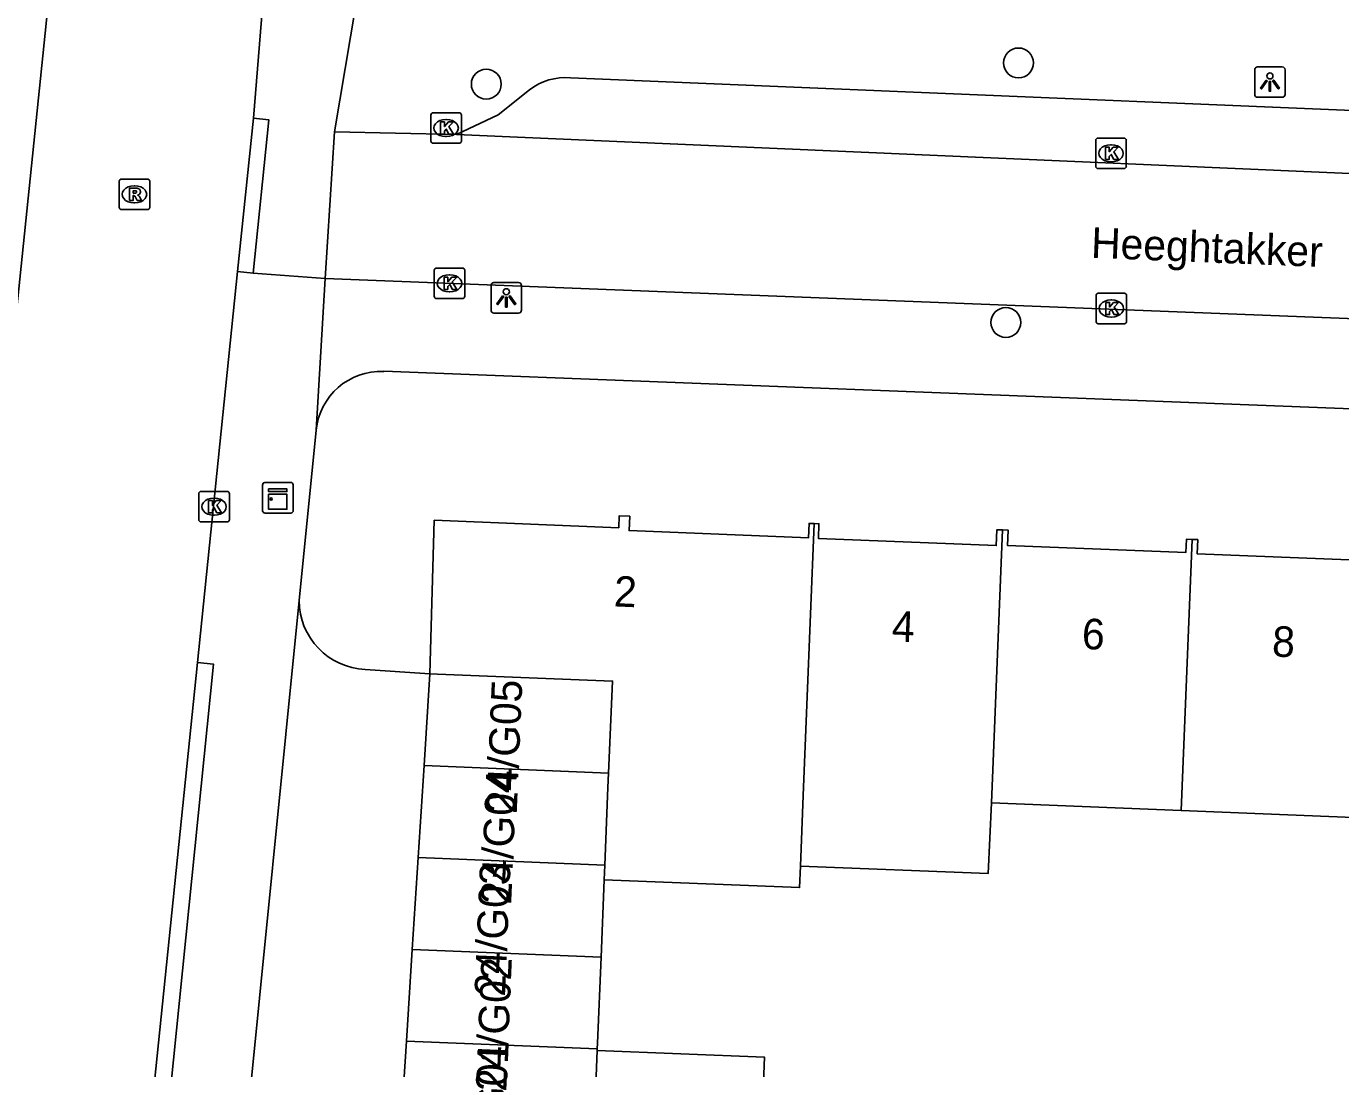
# Model space of a CAD drawing. Extents: x 161355 to 162026, y 386504 to 387459.
# Drawn here: x 161823.29 to 161866.31, y 387026.14 to 387060.25 of the extents above; entities that cross this region are included whole.
import ezdxf

# ---------------------------------------------------------------- set-up
doc = ezdxf.new("R2010")
doc.units = 0
for name, color, linetype in [('IMGEO_Boom', 7, 'Continuous'), ('IMGEO_Kast', 7, 'Continuous'), ('IMGEO_Kolk', 7, 'Continuous'), ('IMGEO_Lichtpunt', 7, 'Continuous'), ('IMGEO_Openbare_ruimte_label', 7, 'Continuous'), ('IMGEO_Pand', 7, 'Continuous'), ('IMGEO_Pand_nummerreeks', 7, 'Continuous'), ('IMGEO_Rijbaan_lokaal_open', 7, 'Continuous'), ('IMGEO_Rioolput', 7, 'Continuous'), ('IMGEO_Voetpad_open', 7, 'Continuous')]:
    doc.layers.add(name, color=color, linetype=linetype)

msp = doc.modelspace()

# ---------------------------------------------------------------- linework, layer by layer
at = {"layer": 'IMGEO_Boom'}
for centre in [(161855.765, 387059.053), (161838.346, 387058.361), (161855.351, 387050.56)]:
    msp.add_circle(centre, 0.489, dxfattribs=at)
at = {"layer": 'IMGEO_Kast'}
for p, q in [((161831.026, 387044.398), (161831.026, 387045.239)), ((161831.026, 387045.239), (161831.026, 387044.398)), ((161831.101, 387045.323), (161831.942, 387045.323)), ((161831.942, 387045.323), (161831.101, 387045.323)), ((161832.026, 387045.248), (161832.026, 387044.407)), ((161832.026, 387044.407), (161832.026, 387045.248)), ((161831.951, 387044.323), (161831.11, 387044.323)), ((161831.11, 387044.323), (161831.951, 387044.323))]:
    msp.add_line(p, q, dxfattribs=at)
for points in [[(161831.221, 387045.113), (161831.821, 387045.113), (161831.821, 387045.028), (161831.221, 387045.028), (161831.221, 387045.113)], [(161831.221, 387044.938), (161831.821, 387044.938), (161831.821, 387044.449), (161831.221, 387044.449), (161831.221, 387044.938)]]:
    msp.add_lwpolyline(points, dxfattribs=at)
msp.add_circle((161831.305, 387044.787), 0.0377, dxfattribs=at)
for centre, start, end in [((161831.104, 387045.245), 92.4484, 184.2845), ((161831.104, 387045.245), 92.4484, 184.2845), ((161831.948, 387045.245), 2.4484, 94.2845), ((161831.948, 387045.245), 2.4484, 94.2845), ((161831.104, 387044.401), 182.4484, 274.2845), ((161831.104, 387044.401), 182.4484, 274.2845), ((161831.948, 387044.401), 272.4484, 4.2845), ((161831.948, 387044.401), 272.4484, 4.2845)]:
    msp.add_arc(centre, 0.0779, start, end, dxfattribs=at)
at = {"layer": 'IMGEO_Kolk'}
for p, q in [((161836.605, 387057.424), (161837.457, 387057.424)), ((161836.53, 387056.498), (161836.53, 387057.35)), ((161837.018, 387057.204), (161837.043, 387057.204)), ((161837.531, 387057.35), (161837.531, 387056.498)), ((161837.041, 387056.644), (161837.016, 387056.644)), ((161858.293, 387055.67), (161858.293, 387056.522)), ((161858.368, 387056.596), (161859.22, 387056.596)), ((161859.294, 387056.522), (161859.294, 387055.67)), ((161837.457, 387056.424), (161836.605, 387056.424)), ((161858.781, 387056.376), (161858.806, 387056.376)), ((161858.804, 387055.816), (161858.779, 387055.816)), ((161859.22, 387055.596), (161858.368, 387055.596)), ((161836.642, 387051.416), (161836.642, 387052.268)), ((161836.717, 387052.342), (161837.569, 387052.342)), ((161837.643, 387052.268), (161837.643, 387051.416)), ((161837.13, 387052.122), (161837.155, 387052.122)), ((161837.153, 387051.562), (161837.128, 387051.562)), ((161858.302, 387050.591), (161858.302, 387051.443)), ((161858.377, 387051.517), (161859.229, 387051.517)), ((161859.303, 387051.443), (161859.303, 387050.591)), ((161837.569, 387051.342), (161836.717, 387051.342)), ((161858.79, 387051.297), (161858.815, 387051.297)), ((161859.229, 387050.517), (161858.377, 387050.517)), ((161858.813, 387050.737), (161858.788, 387050.737)), ((161828.936, 387044.105), (161828.936, 387044.957)), ((161829.011, 387045.031), (161829.863, 387045.031)), ((161829.937, 387044.957), (161829.937, 387044.105)), ((161829.424, 387044.811), (161829.449, 387044.811)), ((161829.447, 387044.251), (161829.422, 387044.251)), ((161829.863, 387044.031), (161829.011, 387044.031))]:
    msp.add_line(p, q, dxfattribs=at)
for points in [[(161836.605, 387057.424), (161837.457, 387057.424)], [(161836.53, 387056.498), (161836.53, 387057.35)], [(161836.851, 387057.124), (161836.974, 387057.124), (161836.974, 387056.973), (161837.104, 387057.124), (161837.268, 387057.124), (161837.122, 387056.973), (161837.275, 387056.724), (161837.123, 387056.724), (161837.038, 387056.888), (161836.974, 387056.821), (161836.974, 387056.724), (161836.851, 387056.724), (161836.851, 387057.124)], [(161837.531, 387057.35), (161837.531, 387056.498)], [(161858.293, 387055.67), (161858.293, 387056.522)], [(161858.368, 387056.596), (161859.22, 387056.596)], [(161859.294, 387056.522), (161859.294, 387055.67)], [(161837.457, 387056.424), (161836.605, 387056.424)], [(161858.614, 387056.296), (161858.737, 387056.296), (161858.737, 387056.145), (161858.867, 387056.296), (161859.031, 387056.296), (161858.885, 387056.145), (161859.038, 387055.896), (161858.886, 387055.896), (161858.801, 387056.06), (161858.737, 387055.993), (161858.737, 387055.896), (161858.614, 387055.896), (161858.614, 387056.296)], [(161859.22, 387055.596), (161858.368, 387055.596)], [(161836.642, 387051.416), (161836.642, 387052.268)], [(161836.717, 387052.342), (161837.569, 387052.342)], [(161837.643, 387052.268), (161837.643, 387051.416)], [(161836.963, 387052.042), (161837.086, 387052.042), (161837.086, 387051.891), (161837.216, 387052.042), (161837.38, 387052.042), (161837.234, 387051.891), (161837.387, 387051.642), (161837.235, 387051.642), (161837.15, 387051.806), (161837.086, 387051.739), (161837.086, 387051.642), (161836.963, 387051.642), (161836.963, 387052.042)], [(161858.302, 387050.591), (161858.302, 387051.443)], [(161858.377, 387051.517), (161859.229, 387051.517)], [(161859.303, 387051.443), (161859.303, 387050.591)], [(161837.569, 387051.342), (161836.717, 387051.342)], [(161858.623, 387051.217), (161858.746, 387051.217), (161858.746, 387051.066), (161858.876, 387051.217), (161859.04, 387051.217), (161858.894, 387051.066), (161859.047, 387050.817), (161858.895, 387050.817), (161858.81, 387050.981), (161858.746, 387050.914), (161858.746, 387050.817), (161858.623, 387050.817), (161858.623, 387051.217)], [(161859.229, 387050.517), (161858.377, 387050.517)], [(161828.936, 387044.105), (161828.936, 387044.957)], [(161829.011, 387045.031), (161829.863, 387045.031)], [(161829.937, 387044.957), (161829.937, 387044.105)], [(161829.257, 387044.731), (161829.38, 387044.731), (161829.38, 387044.58), (161829.51, 387044.731), (161829.674, 387044.731), (161829.528, 387044.58), (161829.681, 387044.331), (161829.529, 387044.331), (161829.444, 387044.495), (161829.38, 387044.428), (161829.38, 387044.331), (161829.257, 387044.331), (161829.257, 387044.731)], [(161829.863, 387044.031), (161829.011, 387044.031)]]:
    msp.add_lwpolyline(points, dxfattribs=at)
for centre, start, end in [((161836.607, 387057.348), 91.552, 178.448), ((161836.607, 387057.348), 91.552, 178.448), ((161837.455, 387057.348), 1.552, 88.448), ((161837.455, 387057.348), 1.552, 88.448), ((161858.37, 387056.52), 91.552, 178.448), ((161858.37, 387056.52), 91.552, 178.448), ((161859.218, 387056.52), 1.552, 88.448), ((161859.218, 387056.52), 1.552, 88.448), ((161836.607, 387056.5), 181.552, 268.448), ((161836.607, 387056.5), 181.552, 268.448), ((161837.455, 387056.5), 271.552, 358.448), ((161837.455, 387056.5), 271.552, 358.448), ((161858.37, 387055.672), 181.552, 268.448), ((161858.37, 387055.672), 181.552, 268.448), ((161859.218, 387055.672), 271.552, 358.448), ((161859.218, 387055.672), 271.552, 358.448), ((161836.719, 387052.266), 91.552, 178.448), ((161836.719, 387052.266), 91.552, 178.448), ((161837.567, 387052.266), 1.552, 88.448), ((161837.567, 387052.266), 1.552, 88.448), ((161836.719, 387051.418), 181.552, 268.448), ((161836.719, 387051.418), 181.552, 268.448), ((161837.567, 387051.418), 271.552, 358.448), ((161837.567, 387051.418), 271.552, 358.448), ((161858.379, 387051.441), 91.552, 178.448), ((161858.379, 387051.441), 91.552, 178.448), ((161859.227, 387051.441), 1.552, 88.448), ((161859.227, 387051.441), 1.552, 88.448), ((161858.379, 387050.593), 181.552, 268.448), ((161858.379, 387050.593), 181.552, 268.448), ((161859.227, 387050.593), 271.552, 358.448), ((161859.227, 387050.593), 271.552, 358.448), ((161829.013, 387044.955), 91.552, 178.448), ((161829.013, 387044.955), 91.552, 178.448), ((161829.861, 387044.955), 1.552, 88.448), ((161829.861, 387044.955), 1.552, 88.448), ((161829.013, 387044.107), 181.552, 268.448), ((161829.013, 387044.107), 181.552, 268.448), ((161829.861, 387044.107), 271.552, 358.448), ((161829.861, 387044.107), 271.552, 358.448)]:
    msp.add_arc(centre, 0.0765, start, end, dxfattribs=at)
for centre, major_axis, ratio, start_param, end_param in [((161837.017, 387056.924), (-0.387, 0.002), 0.722429, 4.712389, 7.853982), ((161837.042, 387056.924), (-0.39, 0.002), 0.717154, 1.570796, 4.712389), ((161858.78, 387056.096), (-0.387, 0.002), 0.722429, 4.712389, 7.853982), ((161858.805, 387056.096), (-0.39, 0.002), 0.717154, 1.570796, 4.712389), ((161837.129, 387051.842), (-0.387, 0.002), 0.722429, 4.712389, 7.853982), ((161837.154, 387051.842), (-0.39, 0.002), 0.717154, 1.570796, 4.712389), ((161858.789, 387051.017), (-0.387, 0.002), 0.722429, 4.712389, 7.853982), ((161858.814, 387051.017), (-0.39, 0.002), 0.717154, 1.570796, 4.712389), ((161829.423, 387044.531), (-0.387, 0.002), 0.722429, 4.712389, 7.853982), ((161829.448, 387044.531), (-0.39, 0.002), 0.717154, 1.570796, 4.712389)]:
    msp.add_ellipse(centre, major_axis=major_axis, ratio=ratio, start_param=start_param, end_param=end_param, dxfattribs=at)
at = {"layer": 'IMGEO_Lichtpunt'}
for p, q in [((161863.495, 387058.831), (161863.495, 387058.024)), ((161863.495, 387058.831), (161863.495, 387058.024)), ((161864.397, 387058.926), (161863.589, 387058.926)), ((161864.397, 387058.926), (161863.589, 387058.926)), ((161864.491, 387058.024), (161864.491, 387058.831)), ((161864.491, 387058.024), (161864.491, 387058.831)), ((161863.589, 387057.93), (161864.397, 387057.93)), ((161863.589, 387057.93), (161864.397, 387057.93)), ((161839.405, 387051.864), (161838.597, 387051.864)), ((161839.405, 387051.864), (161838.597, 387051.864)), ((161838.503, 387051.769), (161838.503, 387050.962)), ((161838.503, 387051.769), (161838.503, 387050.962)), ((161839.499, 387050.962), (161839.499, 387051.769)), ((161839.499, 387050.962), (161839.499, 387051.769)), ((161838.597, 387050.868), (161839.405, 387050.868)), ((161838.597, 387050.868), (161839.405, 387050.868))]:
    msp.add_line(p, q, dxfattribs=at)
for points in [[(161863.869, 387058.495), (161863.908, 387058.467), (161863.72, 387058.205), (161863.682, 387058.232), (161863.869, 387058.495)], [(161863.971, 387058.447), (161864.018, 387058.447), (161864.018, 387058.125), (161863.971, 387058.125), (161863.971, 387058.447)], [(161864.081, 387058.467), (161864.119, 387058.494), (161864.306, 387058.232), (161864.267, 387058.204), (161864.081, 387058.467)], [(161838.877, 387051.433), (161838.916, 387051.405), (161838.728, 387051.143), (161838.69, 387051.17), (161838.877, 387051.433)], [(161838.979, 387051.385), (161839.026, 387051.385), (161839.026, 387051.063), (161838.979, 387051.063), (161838.979, 387051.385)], [(161839.089, 387051.405), (161839.127, 387051.432), (161839.314, 387051.17), (161839.275, 387051.142), (161839.089, 387051.405)]]:
    msp.add_lwpolyline(points, dxfattribs=at)
for centre in [(161863.994, 387058.629), (161839.002, 387051.567)]:
    msp.add_circle(centre, 0.0994, dxfattribs=at)
for centre, start, end in [((161863.589, 387058.831), 90, 180), ((161863.589, 387058.831), 90, 180), ((161864.397, 387058.831), 0, 90), ((161864.397, 387058.831), 0, 90), ((161863.589, 387058.024), 180, 270), ((161863.589, 387058.024), 180, 270), ((161864.397, 387058.024), 270, 0), ((161864.397, 387058.024), 270, 360), ((161838.597, 387051.769), 90, 180), ((161838.597, 387051.769), 90, 180), ((161839.405, 387051.769), 0, 90), ((161839.405, 387051.769), 0, 90), ((161838.597, 387050.962), 180, 270), ((161838.597, 387050.962), 180, 270), ((161839.405, 387050.962), 270, 0), ((161839.405, 387050.962), 270, 360)]:
    msp.add_arc(centre, 0.0946, start, end, dxfattribs=at)
at = {"layer": 'IMGEO_Pand'}
for points in [[(161836.501, 387039.063), (161836.645, 387044.088), (161842.68, 387043.842), (161842.696, 387044.232), (161843.04, 387044.218), (161843.021, 387043.75), (161848.893, 387043.514), (161848.912, 387043.984), (161849.072, 387043.978)], [(161849.072, 387043.978), (161848.718, 387035.083), (161848.626, 387032.769)], [(161849.072, 387043.978), (161849.233, 387043.971), (161849.214, 387043.491), (161855.039, 387043.258), (161855.06, 387043.778), (161855.242, 387043.771)], [(161855.242, 387043.771), (161854.886, 387034.836)], [(161855.242, 387043.771), (161855.424, 387043.764), (161855.404, 387043.265), (161861.24, 387043.03), (161861.258, 387043.467), (161861.445, 387043.459)], [(161861.445, 387043.459), (161861.092, 387034.586)], [(161861.445, 387043.459), (161861.632, 387043.452), (161861.614, 387042.987), (161867.42, 387042.754), (161867.442, 387043.284), (161867.625, 387043.277)], [(161836.501, 387039.063), (161836.309, 387036.056)], [(161842.345, 387035.813), (161842.479, 387038.823), (161836.746, 387039.053), (161836.501, 387039.063)], [(161836.117, 387033.049), (161836.309, 387036.056)], [(161836.309, 387036.056), (161842.345, 387035.813)], [(161842.222, 387032.803), (161842.324, 387035.34), (161842.345, 387035.813)], [(161854.886, 387034.836), (161854.767, 387032.525), (161848.626, 387032.769)], [(161861.092, 387034.586), (161854.886, 387034.836)], [(161861.092, 387034.586), (161867.269, 387034.338)], [(161836.117, 387033.049), (161835.925, 387030.042)], [(161842.222, 387032.803), (161836.117, 387033.049)], [(161842.203, 387032.321), (161842.222, 387032.803)], [(161848.626, 387032.769), (161848.598, 387032.066), (161842.203, 387032.321)], [(161842.101, 387029.793), (161842.203, 387032.321)], [(161835.733, 387027.035), (161835.925, 387030.042)], [(161835.925, 387030.042), (161842.101, 387029.793)], [(161841.98, 387026.783), (161841.988, 387026.975), (161842.101, 387029.793)], [(161835.531, 387023.874), (161835.733, 387027.035)], [(161841.98, 387026.783), (161835.733, 387027.035)], [(161841.978, 387026.73), (161841.853, 387023.623)], [(161841.978, 387026.73), (161841.98, 387026.783)], [(161847.329, 387023.405), (161847.452, 387026.513), (161841.978, 387026.73)]]:
    msp.add_lwpolyline(points, dxfattribs=at)
at = {"layer": 'IMGEO_Rijbaan_lokaal_open'}
for points in [[(161819.356, 387015.932), (161822.363, 387045.09), (161824.742, 387068.09)], [(161830.722, 387057.242), (161831.561, 387067.477)], [(161830.208, 387052.228), (161830.722, 387057.242)], [(161833.077, 387051.994), (161833.373, 387056.795)], [(161833.373, 387056.795), (161837.366, 387056.707)], [(161881.037, 387054.891), (161880.843, 387054.81), (161837.366, 387056.707)], [(161828.897, 387039.434), (161830.208, 387052.228)], [(161884.941, 387049.973), (161833.077, 387051.994)], [(161827.357, 387024.427), (161828.897, 387039.434)]]:
    msp.add_lwpolyline(points, dxfattribs=at)
at = {"layer": 'IMGEO_Rioolput'}
for p, q in [((161826.405, 387055.254), (161827.257, 387055.254)), ((161826.33, 387054.328), (161826.33, 387055.18)), ((161826.818, 387055.034), (161826.843, 387055.034)), ((161827.331, 387055.18), (161827.331, 387054.328)), ((161826.841, 387054.474), (161826.816, 387054.474)), ((161827.257, 387054.254), (161826.405, 387054.254))]:
    msp.add_line(p, q, dxfattribs=at)
for points in [[(161826.405, 387055.254), (161827.257, 387055.254)], [(161826.33, 387054.328), (161826.33, 387055.18)], [(161826.919, 387054.952), (161826.667, 387054.954), (161826.667, 387054.554)], [(161826.845, 387054.873), (161826.791, 387054.873), (161826.791, 387054.792)], [(161827.331, 387055.18), (161827.331, 387054.328)], [(161826.667, 387054.554), (161826.791, 387054.554), (161826.791, 387054.716), (161826.802, 387054.716)], [(161826.791, 387054.792), (161826.843, 387054.792)], [(161826.849, 387054.687), (161826.92, 387054.554), (161827.06, 387054.554), (161826.995, 387054.68)], [(161827.257, 387054.254), (161826.405, 387054.254)]]:
    msp.add_lwpolyline(points, dxfattribs=at)
for centre, radius, start, end in [((161826.407, 387055.178), 0.0765, 91.552, 178.448), ((161826.407, 387055.178), 0.0765, 91.552, 178.448), ((161827.255, 387055.178), 0.0765, 1.552, 88.448), ((161827.255, 387055.178), 0.0765, 1.552, 88.448), ((161826.851, 387054.777), 0.0964, 77.0061, 93.1865), ((161826.865, 387054.834), 0.0378, 276.6634, 79.6772), ((161826.918, 387054.842), 0.109, 350.3612, 89.416), ((161826.916, 387054.842), 0.112, 277.5842, 350.9817), ((161826.801, 387054.663), 0.0533, 26.0293, 88.6989), ((161826.827, 387054.981), 0.19, 274.7715, 282.9687), ((161826.9, 387054.627), 0.108, 29.5134, 73.7905), ((161826.407, 387054.33), 0.0765, 181.552, 268.448), ((161826.407, 387054.33), 0.0765, 181.552, 268.448), ((161827.255, 387054.33), 0.0765, 271.552, 358.448), ((161827.255, 387054.33), 0.0765, 271.552, 358.448)]:
    msp.add_arc(centre, radius, start, end, dxfattribs=at)
for centre, major_axis, ratio, start_param, end_param in [((161826.817, 387054.754), (-0.387, 0.002), 0.722429, 4.712389, 7.853982), ((161826.842, 387054.754), (-0.39, 0.002), 0.717154, 1.570796, 4.712389)]:
    msp.add_ellipse(centre, major_axis=major_axis, ratio=ratio, start_param=start_param, end_param=end_param, dxfattribs=at)
at = {"layer": 'IMGEO_Voetpad_open'}
for points in [[(161834.6, 387064.069), (161833.373, 387056.795)], [(161841.102, 387058.564), (161877.664, 387057.038)], [(161837.366, 387056.707), (161838.73, 387057.358), (161839.757, 387058.171)], [(161830.722, 387057.242), (161831.224, 387057.192), (161830.714, 387052.177)], [(161830.714, 387052.177), (161830.208, 387052.228)], [(161830.714, 387052.177), (161833.077, 387051.994)], [(161833.077, 387051.994), (161832.776, 387047.033)], [(161895.537, 387046.615), (161834.988, 387048.961)], [(161832.776, 387047.033), (161832.223, 387041.459)], [(161832.223, 387041.459), (161830.485, 387024.074)], [(161828.897, 387039.434), (161829.415, 387039.382), (161827.897, 387024.373), (161827.357, 387024.427)], [(161834.385, 387039.206), (161836.501, 387039.063)]]:
    msp.add_lwpolyline(points, dxfattribs=at)
for centre, radius, start, end in [((161840.923, 387056.68), 1.893, 84.5615, 128.0145), ((161834.908, 387046.82), 2.142, 87.856, 174.2954), ((161834.477, 387041.458), 2.254, 179.9712, 267.6672)]:
    msp.add_arc(centre, radius, start, end, dxfattribs=at)

# ---------------------------------------------------------------- texts
at = {"layer": 'IMGEO_Openbare_ruimte_label'}
msp.add_text('Heeghtakker', height=1, rotation=357.7071, dxfattribs=at).set_placement((161858.126, 387052.678))
at = {"layer": 'IMGEO_Pand_nummerreeks'}
for s, rotation, p in [('2', 357.5019, (161842.507, 387041.27)), ('4', 357.7189, (161851.604, 387040.125)), ('6', 357.7189, (161857.826, 387039.878)), ('8', 357.7189, (161864.051, 387039.63)), ('24/G05', 87.5709, (161839.342, 387034.469)), ('24/G04', 87.5709, (161839.16, 387031.503)), ('24/G03', 87.5709, (161838.957, 387028.486)), ('24/G02', 87.5709, (161839, 387025.376)), ('24/G01', 87.5709, (161838.897, 387022.647))]:
    msp.add_text(s, height=1, rotation=rotation, dxfattribs=at).set_placement(p)

doc.saveas('drawing.dxf')
